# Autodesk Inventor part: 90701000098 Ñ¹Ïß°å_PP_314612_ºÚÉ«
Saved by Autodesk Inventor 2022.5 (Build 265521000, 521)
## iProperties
Created: 2025-02
Part Number: 90701000098 Ñ¹Ïß°å_PP_314612_ºÚÉ«
Material: Generic
Document SubType Name: Modeling
Designer: AdminForWorker
Density: 1 g/cm^3
Appearance: Default
Title: 90701000098 Ñ¹Ïß°å_PP_314612_ºÚÉ«
Author: AdminForWorker
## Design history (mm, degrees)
feature "Body1"
body "Solid1"
